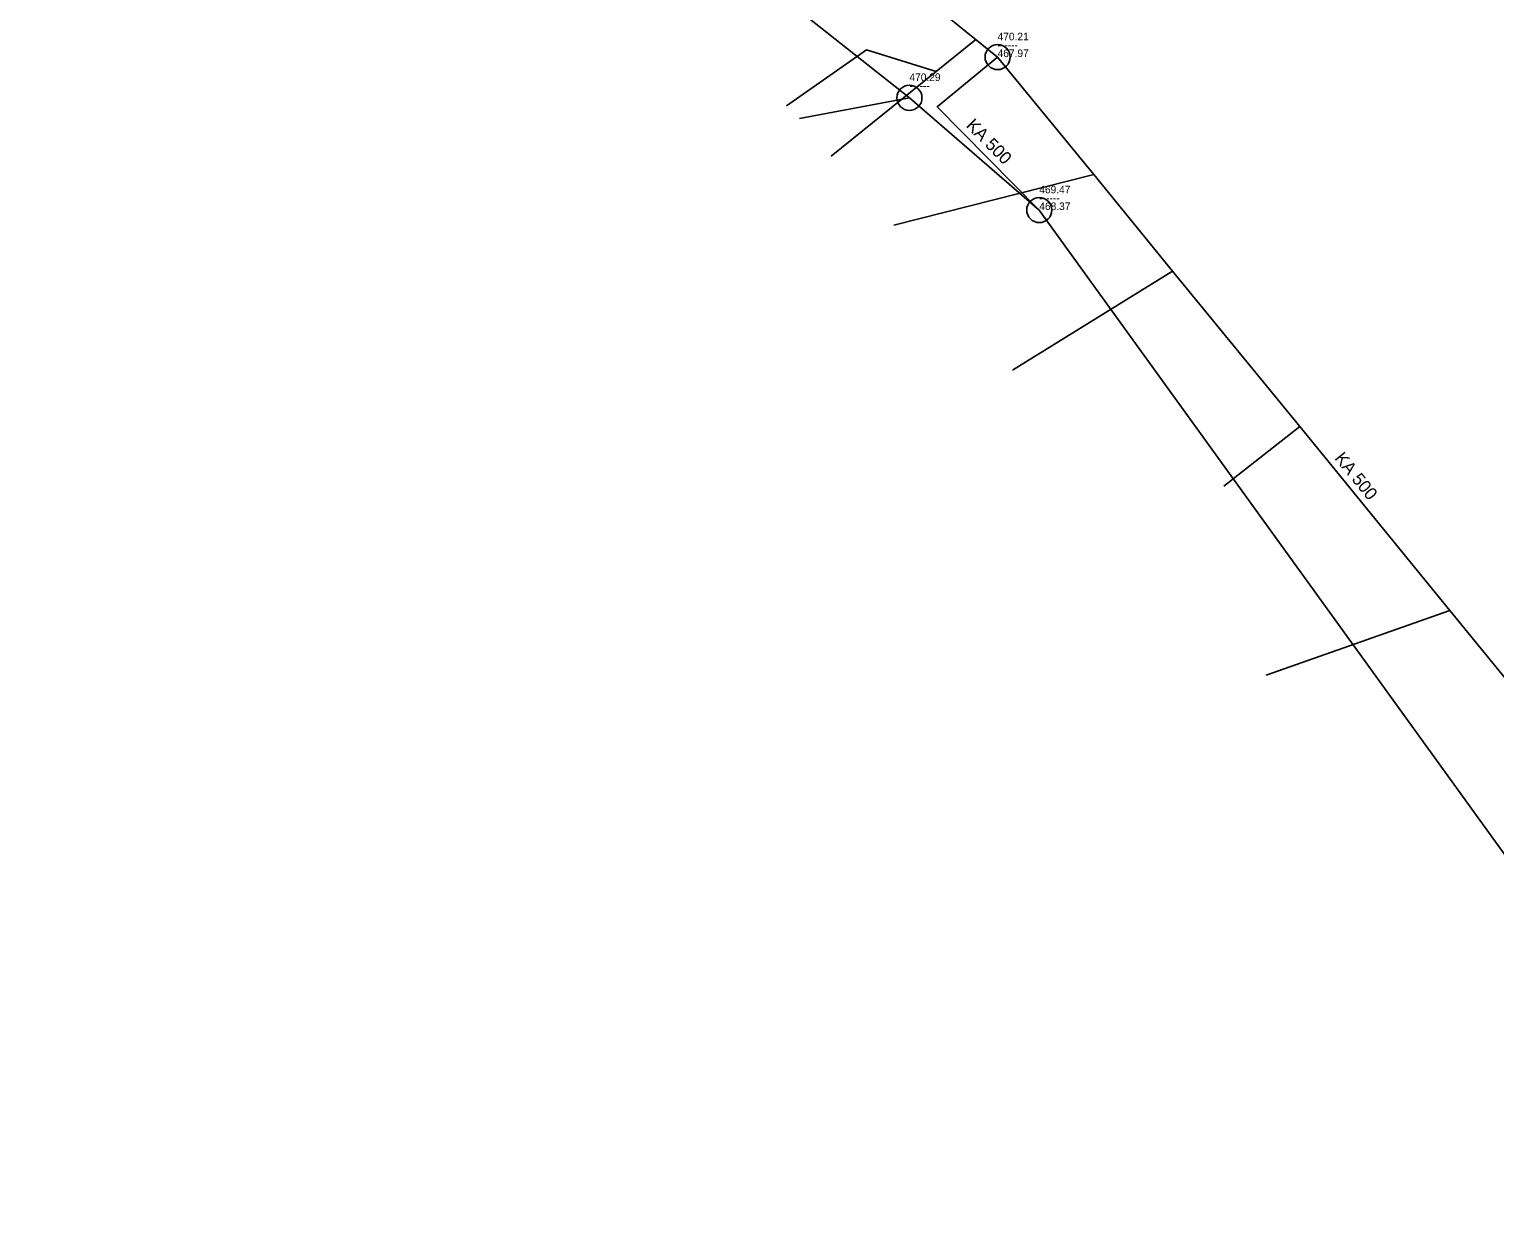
# Model space of a CAD drawing. Extents: x -684724 to -684322, y -1163905 to -1163488.
# Drawn here: x -684597.3 to -684538.9, y -1163743.6 to -1163695.9 of the extents above; entities that cross this region are included whole.
import ezdxf

# ---------------------------------------------------------------- set-up
doc = ezdxf.new("R2010")
doc.units = 0
for name, color, linetype in [('Kanalizační přípojky', 7, 'Continuous'), ('Kanalizační stoka', 7, 'Continuous'), ('Kanalizační šachty', 7, 'Continuous'), ('Popis', 7, 'Continuous')]:
    doc.layers.add(name, color=color, linetype=linetype)

msp = doc.modelspace()

# ---------------------------------------------------------------- linework, layer by layer
at = {"layer": 'Kanalizační přípojky'}
for points in [[(-684565.35, -1163700.9), (-684559.59, -1163696.26)], [(-684567.14, -1163698.9), (-684563.95, -1163696.67), (-684561.17, -1163697.53)], [(-684566.62, -1163699.4), (-684562.24, -1163698.58)], [(-684562.86, -1163703.65), (-684554.9, -1163701.64)], [(-684558.13, -1163709.42), (-684551.76, -1163705.48)], [(-684549.72, -1163714.04), (-684546.7, -1163711.67)], [(-684548.04, -1163721.56), (-684540.72, -1163718.99)]]:
    msp.add_lwpolyline(points, dxfattribs=at)
at = {"layer": 'Kanalizační stoka'}
for points in [[(-684597.28, -1163670.99), (-684566.86, -1163694.94), (-684562.24, -1163698.58)], [(-684564.56, -1163692.24), (-684558.73, -1163696.96)], [(-684558.73, -1163696.96), (-684561.13, -1163698.94), (-684557.07, -1163703.05)], [(-684558.73, -1163696.96), (-684554.9, -1163701.64), (-684551.76, -1163705.48), (-684546.7, -1163711.67), (-684540.72, -1163718.99), (-684532.34, -1163729.24)], [(-684562.24, -1163698.58), (-684557.07, -1163703.05)], [(-684557.07, -1163703.05), (-684536.38, -1163731.69), (-684526.9, -1163744.37), (-684508.95, -1163776.36)]]:
    msp.add_lwpolyline(points, dxfattribs=at)
at = {"layer": 'Kanalizační šachty'}
for centre in [(-684558.73, -1163696.96), (-684562.24, -1163698.58), (-684557.07, -1163703.05)]:
    msp.add_circle(centre, 0.5, dxfattribs=at)

# ---------------------------------------------------------------- texts
at = {"layer": 'Popis'}
for s, height, rotation, p in [('470.21', 0.303, 360, (-684558.73, -1163696.293)), ('------', 0.303, 360, (-684558.73, -1163696.627)), ('467.97', 0.303, 360, (-684558.73, -1163696.96)), ('470.29', 0.303, 0, (-684562.24, -1163697.913)), ('------', 0.303, 0, (-684562.24, -1163698.247)), ('KA 500', 0.5, 314.64936, (-684560.015, -1163699.713)), ('469.47', 0.303, 360, (-684557.07, -1163702.383)), ('468.37', 0.303, 360, (-684557.07, -1163703.05)), ('------', 0.303, 360, (-684557.07, -1163702.717)), ('KA 500', 0.5, 309.24676, (-684545.339, -1163712.94))]:
    msp.add_text(s, height=height, rotation=rotation, dxfattribs=at).set_placement(p)

doc.saveas('drawing.dxf')
